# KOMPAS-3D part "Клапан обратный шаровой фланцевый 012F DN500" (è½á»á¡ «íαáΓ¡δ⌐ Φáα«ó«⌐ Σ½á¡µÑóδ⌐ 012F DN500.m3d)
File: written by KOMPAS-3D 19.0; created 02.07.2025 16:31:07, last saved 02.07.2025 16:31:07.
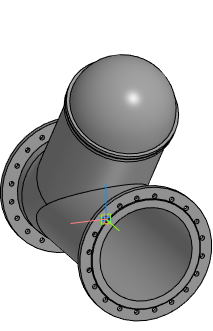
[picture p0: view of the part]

Document properties: Полное имя файла: E:\Dendor Работа Сачек\3D для проектировщиков\5.3 Тип 012F, 012F.Z Клапан обратный шаровой фланцевый\stp_Клапан обратный шаровой фланцевый 012F\Клапан обратный шаровой фланцевый 012F DN500.m3d

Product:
- Part/product: Клапан обратный шаровой фланцевый 012F DN500

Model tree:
1. Операция без истории:1  (labels: Клапан обратный шаровой фланцевый 012F DN500)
